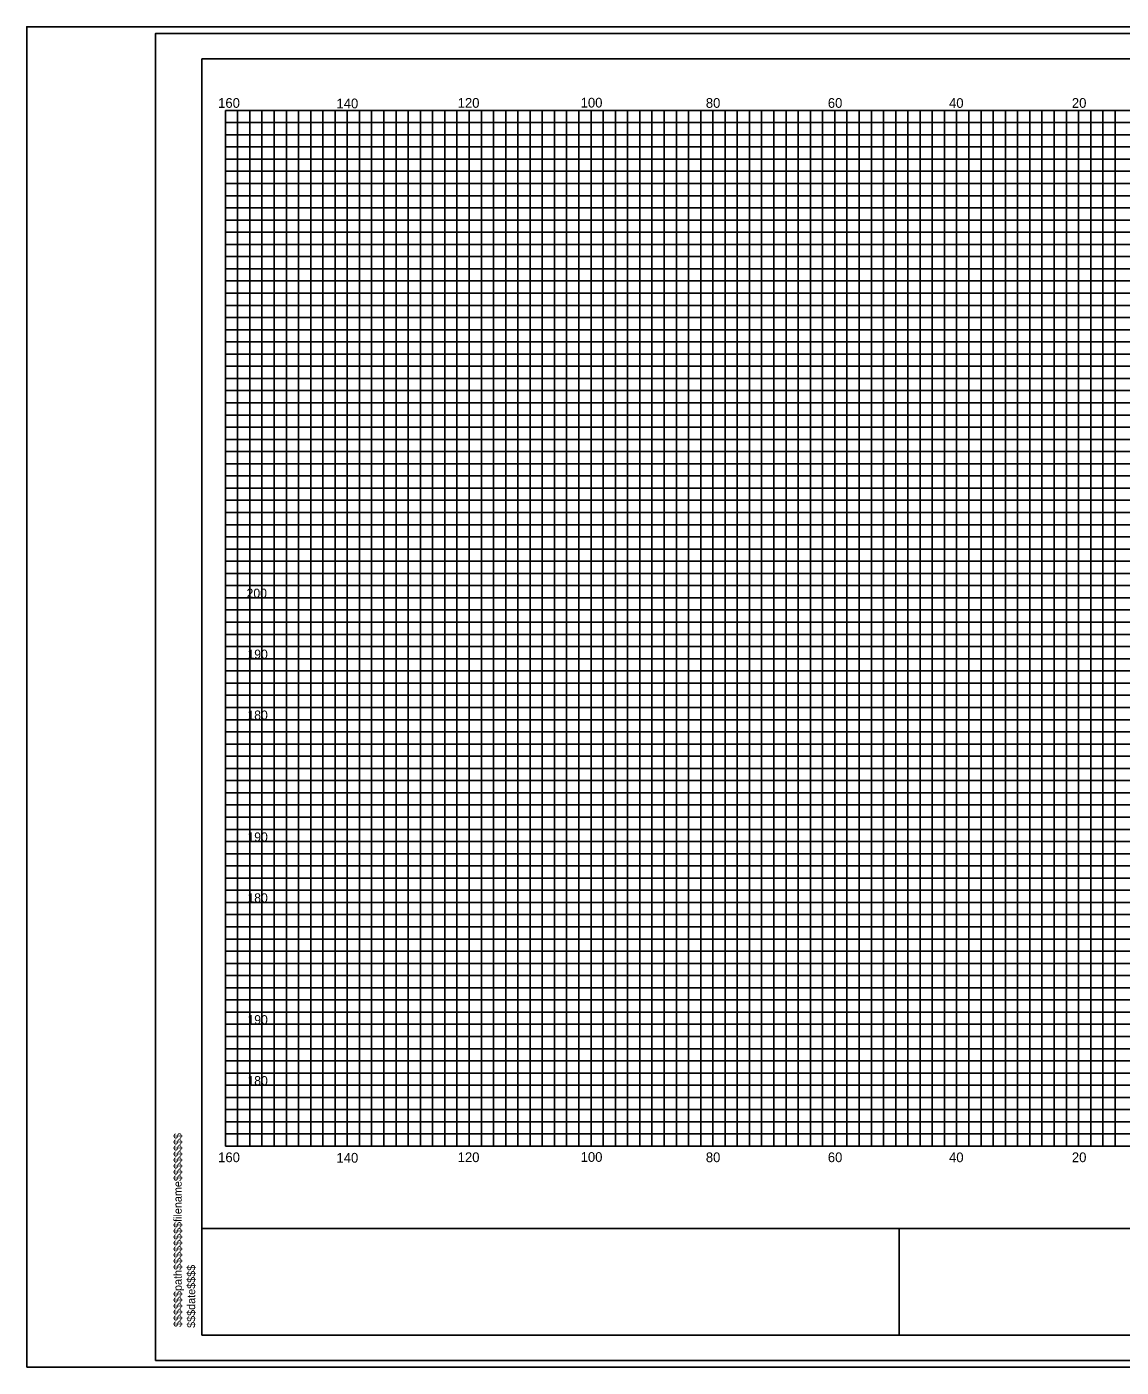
# Model space of a CAD drawing. Extents: x 967 to 1326, y 964 to 2584.
# Drawn here: x 967.4 to 1147, y 2363.7 to 2583.7 of the extents above; entities that cross this region are included whole.
import ezdxf

# ---------------------------------------------------------------- set-up
doc = ezdxf.new("R2010")
doc.units = 0
for name, color, linetype in [('Default', 7, 'Continuous'), ('RD_GPK_XS_Cell', 7, 'Continuous'), ('RD_XS_ExGround', 7, 'Continuous'), ('RD_XS_ExPaveRet', 7, 'Continuous'), ('RD_XS_Misc_Line', 7, 'Continuous'), ('RD_XS_TX_Elev_EX', 7, 'Continuous')]:
    doc.layers.add(name, color=color, linetype=linetype)

msp = doc.modelspace()

# ---------------------------------------------------------------- linework, layer by layer
at = {"layer": 'RD_GPK_XS_Cell'}
for p, q in [((1000, 2570), (1320, 2570)), ((1000, 2400), (1000, 2570)), ((1010, 2400), (1010, 2570)), ((1020, 2400), (1020, 2570)), ((1030, 2400), (1030, 2570)), ((1040, 2400), (1040, 2570)), ((1050, 2400), (1050, 2570)), ((1060, 2400), (1060, 2570)), ((1070, 2400), (1070, 2570)), ((1080, 2400), (1080, 2570)), ((1090, 2400), (1090, 2570)), ((1100, 2400), (1100, 2570)), ((1110, 2400), (1110, 2570)), ((1120, 2400), (1120, 2570)), ((1130, 2400), (1130, 2570)), ((1140, 2400), (1140, 2570)), ((1000, 2560), (1320, 2560)), ((1000, 2550), (1320, 2550)), ((1000, 2540), (1320, 2540)), ((1000, 2530), (1320, 2530)), ((1000, 2520), (1320, 2520)), ((1000, 2510), (1320, 2510)), ((1000, 2500), (1320, 2500)), ((1000, 2490), (1320, 2490)), ((1000, 2480), (1320, 2480)), ((1000, 2470), (1320, 2470)), ((1000, 2460), (1320, 2460)), ((1000, 2450), (1320, 2450)), ((1000, 2440), (1320, 2440)), ((1000, 2430), (1320, 2430)), ((1000, 2420), (1320, 2420)), ((1000, 2410), (1320, 2410)), ((1000, 2400), (1320, 2400))]:
    msp.add_line(p, q, dxfattribs=at)
at = {"layer": 'RD_XS_ExGround'}
for p, q in [((1002, 2400), (1002, 2570)), ((1004, 2400), (1004, 2570)), ((1006, 2400), (1006, 2570)), ((1008, 2400), (1008, 2570)), ((1012, 2400), (1012, 2570)), ((1014, 2400), (1014, 2570)), ((1016, 2400), (1016, 2570)), ((1018, 2400), (1018, 2570)), ((1022, 2400), (1022, 2570)), ((1024, 2400), (1024, 2570)), ((1026, 2400), (1026, 2570)), ((1028, 2400), (1028, 2570)), ((1032, 2400), (1032, 2570)), ((1034, 2400), (1034, 2570)), ((1036, 2400), (1036, 2570)), ((1038, 2400), (1038, 2570)), ((1042, 2400), (1042, 2570)), ((1044, 2400), (1044, 2570)), ((1046, 2400), (1046, 2570)), ((1048, 2400), (1048, 2570)), ((1052, 2400), (1052, 2570)), ((1054, 2400), (1054, 2570)), ((1056, 2400), (1056, 2570)), ((1058, 2400), (1058, 2570)), ((1062, 2400), (1062, 2570)), ((1064, 2400), (1064, 2570)), ((1066, 2400), (1066, 2570)), ((1068, 2400), (1068, 2570)), ((1072, 2400), (1072, 2570)), ((1074, 2400), (1074, 2570)), ((1076, 2400), (1076, 2570)), ((1078, 2400), (1078, 2570)), ((1082, 2400), (1082, 2570)), ((1084, 2400), (1084, 2570)), ((1086, 2400), (1086, 2570)), ((1088, 2400), (1088, 2570)), ((1092, 2400), (1092, 2570)), ((1094, 2400), (1094, 2570)), ((1096, 2400), (1096, 2570)), ((1098, 2400), (1098, 2570)), ((1102, 2400), (1102, 2570)), ((1104, 2400), (1104, 2570)), ((1106, 2400), (1106, 2570)), ((1108, 2400), (1108, 2570)), ((1112, 2400), (1112, 2570)), ((1114, 2400), (1114, 2570)), ((1116, 2400), (1116, 2570)), ((1118, 2400), (1118, 2570)), ((1122, 2400), (1122, 2570)), ((1124, 2400), (1124, 2570)), ((1126, 2400), (1126, 2570)), ((1128, 2400), (1128, 2570)), ((1132, 2400), (1132, 2570)), ((1134, 2400), (1134, 2570)), ((1136, 2400), (1136, 2570)), ((1138, 2400), (1138, 2570)), ((1142, 2400), (1142, 2570)), ((1144, 2400), (1144, 2570)), ((1146, 2400), (1146, 2570)), ((1000, 2568), (1320, 2568)), ((1000, 2566), (1320, 2566)), ((1000, 2564), (1320, 2564)), ((1000, 2562), (1320, 2562)), ((1000, 2558), (1320, 2558)), ((1000, 2556), (1320, 2556)), ((1000, 2554), (1320, 2554)), ((1000, 2552), (1320, 2552)), ((1000, 2548), (1320, 2548)), ((1000, 2546), (1320, 2546)), ((1000, 2544), (1320, 2544)), ((1000, 2542), (1320, 2542)), ((1000, 2538), (1320, 2538)), ((1000, 2536), (1320, 2536)), ((1000, 2534), (1320, 2534)), ((1000, 2532), (1320, 2532)), ((1000, 2528), (1320, 2528)), ((1000, 2526), (1320, 2526)), ((1000, 2524), (1320, 2524)), ((1000, 2522), (1320, 2522)), ((1000, 2518), (1320, 2518)), ((1000, 2516), (1320, 2516)), ((1000, 2514), (1320, 2514)), ((1000, 2512), (1320, 2512)), ((1000, 2508), (1320, 2508)), ((1000, 2506), (1320, 2506)), ((1000, 2504), (1320, 2504)), ((1000, 2502), (1320, 2502)), ((1000, 2498), (1320, 2498)), ((1000, 2496), (1320, 2496)), ((1000, 2494), (1320, 2494)), ((1000, 2492), (1320, 2492)), ((1000, 2488), (1320, 2488)), ((1000, 2486), (1320, 2486)), ((1000, 2484), (1320, 2484)), ((1000, 2482), (1320, 2482)), ((1000, 2478), (1320, 2478)), ((1000, 2476), (1320, 2476)), ((1000, 2474), (1320, 2474)), ((1000, 2472), (1320, 2472)), ((1000, 2468), (1320, 2468)), ((1000, 2466), (1320, 2466)), ((1000, 2464), (1320, 2464)), ((1000, 2462), (1320, 2462)), ((1000, 2458), (1320, 2458)), ((1000, 2456), (1320, 2456)), ((1000, 2454), (1320, 2454)), ((1000, 2452), (1320, 2452)), ((1000, 2448), (1320, 2448)), ((1000, 2446), (1320, 2446)), ((1000, 2444), (1320, 2444)), ((1000, 2442), (1320, 2442)), ((1000, 2438), (1320, 2438)), ((1000, 2436), (1320, 2436)), ((1000, 2434), (1320, 2434)), ((1000, 2432), (1320, 2432)), ((1000, 2428), (1320, 2428)), ((1000, 2426), (1320, 2426)), ((1000, 2424), (1320, 2424)), ((1000, 2422), (1320, 2422)), ((1000, 2418), (1320, 2418)), ((1000, 2416), (1320, 2416)), ((1000, 2414), (1320, 2414)), ((1000, 2412), (1320, 2412)), ((1000, 2408), (1320, 2408)), ((1000, 2406), (1320, 2406)), ((1000, 2404), (1320, 2404)), ((1000, 2402), (1320, 2402))]:
    msp.add_line(p, q, dxfattribs=at)
at = {"layer": 'RD_XS_ExPaveRet'}
for points in [[(967.41, 2363.72), (1326.28, 2363.72), (1326.28, 2583.72), (967.41, 2583.72)], [(988.52, 2364.84), (1326.28, 2364.84), (1326.28, 2582.6), (988.52, 2582.6)]]:
    msp.add_lwpolyline(points, close=True, dxfattribs=at)
at = {"layer": 'RD_XS_TX_Elev_EX'}
for p, q in [((996.11, 2368.98), (996.11, 2578.46)), ((996.11, 2578.46), (1323.89, 2578.46)), ((996.11, 2386.49), (1323.89, 2386.49)), ((1110.59, 2368.98), (1110.59, 2386.56)), ((1323.89, 2368.98), (996.11, 2368.98))]:
    msp.add_line(p, q, dxfattribs=at)

# ---------------------------------------------------------------- texts
at = {"layer": 'Default'}
for s, p in [('200', (1003.47, 2490)), ('190', (1003.61, 2480)), ('180', (1003.61, 2470)), ('190', (1003.61, 2450)), ('180', (1003.61, 2440)), ('190', (1003.61, 2420)), ('180', (1003.61, 2410))]:
    msp.add_text(s, height=1.5, dxfattribs=at).set_placement(p)
for s, p in [('$$$$$$path$$$$$$$$filename$$$$$$$$', (992.83, 2370.31)), ('$$$date$$$$', (995.04, 2370.17))]:
    msp.add_text(s, height=1.3258, rotation=90, dxfattribs=at).set_placement(p)
at = {"layer": 'RD_XS_Misc_Line'}
for s, p in [('160', (998.81, 2570.42)), ('140', (1018.23, 2570.34)), ('120', (1038.12, 2570.43)), ('100', (1058.3, 2570.47)), ('80', (1078.84, 2570.42)), ('60', (1098.86, 2570.42)), ('40', (1118.75, 2570.41)), ('20', (1138.91, 2570.42)), ('160', (998.81, 2397.37)), ('140', (1018.23, 2397.29)), ('120', (1038.12, 2397.38)), ('100', (1058.3, 2397.42)), ('80', (1078.84, 2397.37)), ('60', (1098.86, 2397.37)), ('40', (1118.75, 2397.36)), ('20', (1138.91, 2397.37))]:
    msp.add_text(s, height=1.6, dxfattribs=at).set_placement(p)

doc.saveas('drawing.dxf')
